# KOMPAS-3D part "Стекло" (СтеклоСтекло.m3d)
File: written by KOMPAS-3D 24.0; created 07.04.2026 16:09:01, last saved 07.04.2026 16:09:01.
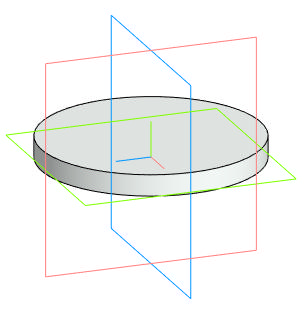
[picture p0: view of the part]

Document properties: Автор: Main; Полное имя файла: D:\DN.ru Аутсерс\Стекло смотровое DN.ru\Исходники\Стекло смотровое DN.ru SG2-34G-F тип В ГОСТ 21836-2021 Ду32 Ру40, углеродистая сталь, фланцевое\СтеклоСтекло.m3d

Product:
- Body: Твердое тело1  | qty 1
- Part/product: Стекло

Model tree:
1. Твердое тело1  (labels: Твердое тело1)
